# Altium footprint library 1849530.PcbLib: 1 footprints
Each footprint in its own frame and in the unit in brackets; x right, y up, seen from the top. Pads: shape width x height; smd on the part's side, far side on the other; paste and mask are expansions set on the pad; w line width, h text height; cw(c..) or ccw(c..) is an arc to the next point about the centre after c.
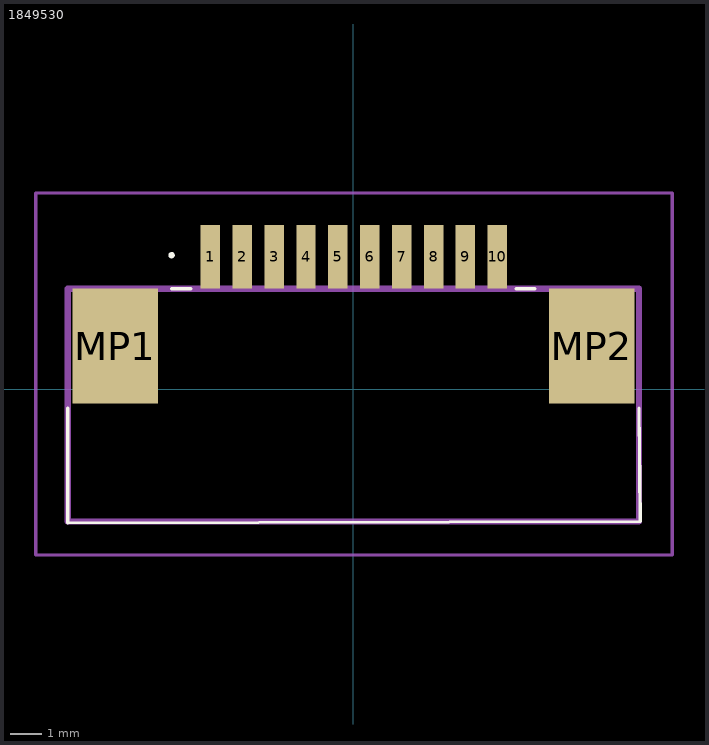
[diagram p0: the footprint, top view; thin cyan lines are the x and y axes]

## 1849530 [mm]
pads (12):
  rect 0.61x2 smd: 1(-4.485,4.15) 2(-3.485,4.15) 3(-2.485,4.15) 4(-1.485,4.15) 5(-0.485,4.15) 6(0.515,4.15) 7(1.515,4.15) 8(2.515,4.15) 9(3.515,4.15) 10(4.515,4.15)
  rect 2.68x3.6 smd: MP1(-7.475,1.35) MP2(7.475,1.35)
Top Overlay:
  lines w0.1: -8.96,-0.6 -8.96,-4.2 9,-4.15 8.96,-0.6 ; -5.7,3.15 -5.1,3.15 ; 5.1,3.15 5.7,3.15 ; -5.7,4.15 -5.7,4.15 ; -5.7,4.15 ccw(c-5.7,4.2) -5.7,4.25 ; -5.7,4.15 cw(c-5.7,4.2) -5.7,4.25 ; -5.7,4.25 -5.7,4.25
Mechanical 15:
  lines w0.2: -8.96,-4.15 8.96,-4.15 8.96,3.15 -8.96,3.15 -8.96,-4.15
Mechanical 20:
  lines w0.1: -9.96,-5.2 10,-5.2 10,6.15 -9.96,6.15 -9.96,-5.2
